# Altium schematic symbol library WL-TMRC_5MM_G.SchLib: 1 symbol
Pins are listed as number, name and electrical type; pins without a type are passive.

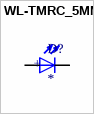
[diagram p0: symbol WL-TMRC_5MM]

## WL-TMRC_5MM
designator D?
MF: {'manufacturer': u'W\xfcrth Elektronik'}; MP: 151051VS04000
footprint WL-TMRC_5MM
pins: 1 POS, 2 NEG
